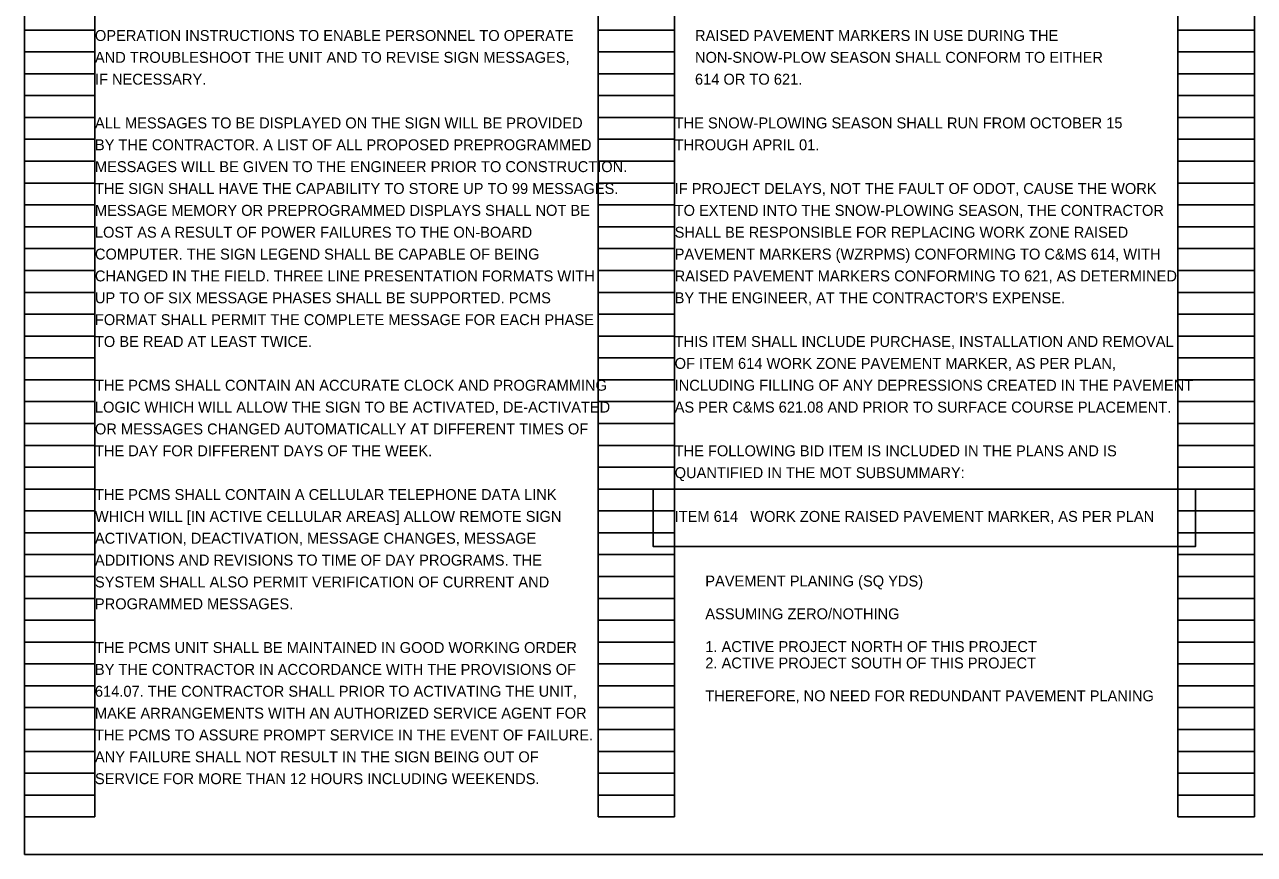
# Model space of a CAD drawing. Extents: x 1820207 to 1820557, y 740216 to 740315.
# Drawn here: x 1820297.23 to 1820312.97, y 740254.74 to 740265.37 of the extents above; entities that cross this region are included whole.
import ezdxf

# ---------------------------------------------------------------- set-up
doc = ezdxf.new("R2010")
doc.units = 0
for name, color, linetype in [('SC_Scratch1', 7, 'Continuous'), ('SC_Scratch2', 7, 'Continuous'), ('SC_Shading1', 7, 'Continuous'), ('SH_Text', 7, 'Continuous')]:
    doc.layers.add(name, color=color, linetype=linetype)

msp = doc.modelspace()

# ---------------------------------------------------------------- linework, layer by layer
at = {"layer": 'SC_Scratch1'}
for p, q in [((1820297.234, 740255.222), (1820297.234, 740275.382)), ((1820298.134, 740255.222), (1820298.134, 740275.382)), ((1820304.574, 740255.222), (1820304.574, 740275.382)), ((1820305.554, 740255.222), (1820305.554, 740275.382)), ((1820311.994, 740255.222), (1820311.994, 740275.382)), ((1820312.974, 740255.222), (1820312.974, 740275.382)), ((1820297.234, 740265.302), (1820298.134, 740265.302)), ((1820304.574, 740265.302), (1820305.554, 740265.302)), ((1820311.994, 740265.302), (1820312.974, 740265.302)), ((1820297.234, 740265.022), (1820298.134, 740265.022)), ((1820304.574, 740265.022), (1820305.554, 740265.022)), ((1820311.994, 740265.022), (1820312.974, 740265.022)), ((1820297.234, 740264.742), (1820298.134, 740264.742)), ((1820304.574, 740264.742), (1820305.554, 740264.742)), ((1820311.994, 740264.742), (1820312.974, 740264.742)), ((1820297.234, 740264.462), (1820298.134, 740264.462)), ((1820304.574, 740264.462), (1820305.554, 740264.462)), ((1820311.994, 740264.462), (1820312.974, 740264.462)), ((1820297.234, 740264.182), (1820298.134, 740264.182)), ((1820304.574, 740264.182), (1820305.554, 740264.182)), ((1820311.994, 740264.182), (1820312.974, 740264.182)), ((1820297.234, 740263.902), (1820298.134, 740263.902)), ((1820304.574, 740263.902), (1820305.554, 740263.902)), ((1820311.994, 740263.902), (1820312.974, 740263.902)), ((1820297.234, 740263.622), (1820298.134, 740263.622)), ((1820304.574, 740263.622), (1820305.554, 740263.622)), ((1820311.994, 740263.622), (1820312.974, 740263.622)), ((1820297.234, 740263.342), (1820298.134, 740263.342)), ((1820304.574, 740263.342), (1820305.554, 740263.342)), ((1820311.994, 740263.342), (1820312.974, 740263.342)), ((1820297.234, 740263.062), (1820298.134, 740263.062)), ((1820304.574, 740263.062), (1820305.554, 740263.062)), ((1820311.994, 740263.062), (1820312.974, 740263.062)), ((1820297.234, 740262.782), (1820298.134, 740262.782)), ((1820304.574, 740262.782), (1820305.554, 740262.782)), ((1820311.994, 740262.782), (1820312.974, 740262.782)), ((1820297.234, 740262.502), (1820298.134, 740262.502)), ((1820304.574, 740262.502), (1820305.554, 740262.502)), ((1820311.994, 740262.502), (1820312.974, 740262.502)), ((1820297.234, 740262.222), (1820298.134, 740262.222)), ((1820304.574, 740262.222), (1820305.554, 740262.222)), ((1820311.994, 740262.222), (1820312.974, 740262.222)), ((1820297.234, 740261.942), (1820298.134, 740261.942)), ((1820304.574, 740261.942), (1820305.554, 740261.942)), ((1820311.994, 740261.942), (1820312.974, 740261.942)), ((1820297.234, 740261.662), (1820298.134, 740261.662)), ((1820304.574, 740261.662), (1820305.554, 740261.662)), ((1820311.994, 740261.662), (1820312.974, 740261.662)), ((1820297.234, 740261.382), (1820298.134, 740261.382)), ((1820304.574, 740261.382), (1820305.554, 740261.382)), ((1820311.994, 740261.382), (1820312.974, 740261.382)), ((1820297.234, 740261.102), (1820298.134, 740261.102)), ((1820304.574, 740261.102), (1820305.554, 740261.102)), ((1820311.994, 740261.102), (1820312.974, 740261.102)), ((1820297.234, 740260.822), (1820298.134, 740260.822)), ((1820304.574, 740260.822), (1820305.554, 740260.822)), ((1820311.994, 740260.822), (1820312.974, 740260.822)), ((1820297.234, 740260.542), (1820298.134, 740260.542)), ((1820304.574, 740260.542), (1820305.554, 740260.542)), ((1820311.994, 740260.542), (1820312.974, 740260.542)), ((1820297.234, 740260.262), (1820298.134, 740260.262)), ((1820304.574, 740260.262), (1820305.554, 740260.262)), ((1820311.994, 740260.262), (1820312.974, 740260.262)), ((1820297.234, 740259.982), (1820298.134, 740259.982)), ((1820304.574, 740259.982), (1820305.554, 740259.982)), ((1820311.994, 740259.982), (1820312.974, 740259.982)), ((1820297.234, 740259.702), (1820298.134, 740259.702)), ((1820304.574, 740259.702), (1820305.554, 740259.702)), ((1820311.994, 740259.702), (1820312.974, 740259.702)), ((1820297.234, 740259.422), (1820298.134, 740259.422)), ((1820304.574, 740259.422), (1820305.554, 740259.422)), ((1820311.994, 740259.422), (1820312.974, 740259.422)), ((1820297.234, 740259.142), (1820298.134, 740259.142)), ((1820304.574, 740259.142), (1820305.554, 740259.142)), ((1820311.994, 740259.142), (1820312.974, 740259.142)), ((1820297.234, 740258.862), (1820298.134, 740258.862)), ((1820304.574, 740258.862), (1820305.554, 740258.862)), ((1820311.994, 740258.862), (1820312.974, 740258.862)), ((1820297.234, 740258.582), (1820298.134, 740258.582)), ((1820304.574, 740258.582), (1820305.554, 740258.582)), ((1820311.994, 740258.582), (1820312.974, 740258.582)), ((1820297.234, 740258.302), (1820298.134, 740258.302)), ((1820304.574, 740258.302), (1820305.554, 740258.302)), ((1820311.994, 740258.302), (1820312.974, 740258.302)), ((1820297.234, 740258.022), (1820298.134, 740258.022)), ((1820304.574, 740258.022), (1820305.554, 740258.022)), ((1820311.994, 740258.022), (1820312.974, 740258.022)), ((1820297.234, 740257.742), (1820298.134, 740257.742)), ((1820304.574, 740257.742), (1820305.554, 740257.742)), ((1820311.994, 740257.742), (1820312.974, 740257.742)), ((1820297.234, 740257.462), (1820298.134, 740257.462)), ((1820304.574, 740257.462), (1820305.554, 740257.462)), ((1820311.994, 740257.462), (1820312.974, 740257.462)), ((1820297.234, 740257.182), (1820298.134, 740257.182)), ((1820304.574, 740257.182), (1820305.554, 740257.182)), ((1820311.994, 740257.182), (1820312.974, 740257.182)), ((1820297.234, 740256.902), (1820298.134, 740256.902)), ((1820304.574, 740256.902), (1820305.554, 740256.902)), ((1820311.994, 740256.902), (1820312.974, 740256.902)), ((1820297.234, 740256.622), (1820298.134, 740256.622)), ((1820304.574, 740256.622), (1820305.554, 740256.622)), ((1820311.994, 740256.622), (1820312.974, 740256.622)), ((1820297.234, 740256.342), (1820298.134, 740256.342)), ((1820304.574, 740256.342), (1820305.554, 740256.342)), ((1820311.994, 740256.342), (1820312.974, 740256.342)), ((1820297.234, 740256.062), (1820298.134, 740256.062)), ((1820304.574, 740256.062), (1820305.554, 740256.062)), ((1820311.994, 740256.062), (1820312.974, 740256.062)), ((1820297.234, 740255.782), (1820298.134, 740255.782)), ((1820304.574, 740255.782), (1820305.554, 740255.782)), ((1820311.994, 740255.782), (1820312.974, 740255.782)), ((1820297.234, 740255.502), (1820298.134, 740255.502)), ((1820304.574, 740255.502), (1820305.554, 740255.502)), ((1820311.994, 740255.502), (1820312.974, 740255.502)), ((1820297.234, 740255.222), (1820298.134, 740255.222)), ((1820304.574, 740255.222), (1820305.554, 740255.222)), ((1820311.994, 740255.222), (1820312.974, 740255.222))]:
    msp.add_line(p, q, dxfattribs=at)
at = {"layer": 'SC_Scratch2'}
msp.add_lwpolyline([(1820297.234, 740275.742), (1820327.734, 740275.742), (1820327.734, 740254.742), (1820297.234, 740254.742)], close=True, dxfattribs=at)
at = {"layer": 'SC_Shading1'}
msp.add_lwpolyline([(1820305.279, 740259.422), (1820312.218, 740259.422), (1820312.218, 740258.686), (1820305.279, 740258.686)], close=True, dxfattribs=at)

# ---------------------------------------------------------------- texts
for s, p in [('PAVEMENT PLANING (SQ YDS)', (1820305.946, 740258.174)), ('ASSUMING ZERO/NOTHING', (1820305.946, 740257.754)), ('1. ACTIVE PROJECT NORTH OF THIS PROJECT', (1820305.946, 740257.334)), ('2. ACTIVE PROJECT SOUTH OF THIS PROJECT', (1820305.946, 740257.124)), ('THEREFORE, NO NEED FOR REDUNDANT PAVEMENT PLANING', (1820305.946, 740256.704))]:
    msp.add_text(s, height=0.14, dxfattribs=at).set_placement(p)
at = {"layer": 'SH_Text'}
for s, p in [('OPERATION INSTRUCTIONS TO ENABLE PERSONNEL TO OPERATE ', (1820298.134, 740265.162)), ('     RAISED PAVEMENT MARKERS IN USE DURING THE', (1820305.554, 740265.162)), ('AND TROUBLESHOOT THE UNIT AND TO REVISE SIGN MESSAGES, ', (1820298.134, 740264.882)), ('     NON-SNOW-PLOW SEASON SHALL CONFORM TO EITHER', (1820305.554, 740264.882)), ('IF NECESSARY.', (1820298.134, 740264.602)), ('     614 OR TO 621.', (1820305.554, 740264.602)), ('ALL MESSAGES TO BE DISPLAYED ON THE SIGN WILL BE PROVIDED ', (1820298.134, 740264.042)), ('THE SNOW-PLOWING SEASON SHALL RUN FROM OCTOBER 15', (1820305.554, 740264.042)), ('BY THE CONTRACTOR. A LIST OF ALL PROPOSED PREPROGRAMMED ', (1820298.134, 740263.762)), ('THROUGH APRIL 01.', (1820305.554, 740263.762)), ('MESSAGES WILL BE GIVEN TO THE ENGINEER PRIOR TO CONSTRUCTION. ', (1820298.134, 740263.482)), ('THE SIGN SHALL HAVE THE CAPABILITY TO STORE UP TO 99 MESSAGES. ', (1820298.134, 740263.202)), ('IF PROJECT DELAYS, NOT THE FAULT OF ODOT, CAUSE THE WORK ', (1820305.554, 740263.202)), ('MESSAGE MEMORY OR PREPROGRAMMED DISPLAYS SHALL NOT BE ', (1820298.134, 740262.922)), ('TO EXTEND INTO THE SNOW-PLOWING SEASON, THE CONTRACTOR ', (1820305.554, 740262.922)), ('LOST AS A RESULT OF POWER FAILURES TO THE ON-BOARD ', (1820298.134, 740262.642)), ('SHALL BE RESPONSIBLE FOR REPLACING WORK ZONE RAISED ', (1820305.554, 740262.642)), ('COMPUTER. THE SIGN LEGEND SHALL BE CAPABLE OF BEING ', (1820298.134, 740262.362)), ('PAVEMENT MARKERS (WZRPMS) CONFORMING TO C&MS 614, WITH ', (1820305.554, 740262.362)), ('CHANGED IN THE FIELD. THREE LINE PRESENTATION FORMATS WITH ', (1820298.134, 740262.082)), ('RAISED PAVEMENT MARKERS CONFORMING TO 621, AS DETERMINED ', (1820305.554, 740262.082)), ('UP TO OF SIX MESSAGE PHASES SHALL BE SUPPORTED. PCMS ', (1820298.134, 740261.802)), ("BY THE ENGINEER, AT THE CONTRACTOR'S EXPENSE.", (1820305.554, 740261.802)), ('FORMAT SHALL PERMIT THE COMPLETE MESSAGE FOR EACH PHASE ', (1820298.134, 740261.522)), ('TO BE READ AT LEAST TWICE. ', (1820298.134, 740261.242)), ('THIS ITEM SHALL INCLUDE PURCHASE, INSTALLATION AND REMOVAL', (1820305.554, 740261.242)), ('OF ITEM 614 WORK ZONE PAVEMENT MARKER, AS PER PLAN, ', (1820305.554, 740260.962)), ('THE PCMS SHALL CONTAIN AN ACCURATE CLOCK AND PROGRAMMING ', (1820298.134, 740260.682)), ('INCLUDING FILLING OF ANY DEPRESSIONS CREATED IN THE PAVEMENT ', (1820305.554, 740260.682)), ('LOGIC WHICH WILL ALLOW THE SIGN TO BE ACTIVATED, DE-ACTIVATED ', (1820298.134, 740260.402)), ('AS PER C&MS 621.08 AND PRIOR TO SURFACE COURSE PLACEMENT.', (1820305.554, 740260.402)), ('OR MESSAGES CHANGED AUTOMATICALLY AT DIFFERENT TIMES OF ', (1820298.134, 740260.122)), ('THE DAY FOR DIFFERENT DAYS OF THE WEEK.', (1820298.134, 740259.842)), ('THE FOLLOWING BID ITEM IS INCLUDED IN THE PLANS AND IS ', (1820305.554, 740259.842)), ('QUANTIFIED IN THE MOT SUBSUMMARY:', (1820305.554, 740259.562)), ('THE PCMS SHALL CONTAIN A CELLULAR TELEPHONE DATA LINK ', (1820298.134, 740259.282)), ('WHICH WILL [IN ACTIVE CELLULAR AREAS] ALLOW REMOTE SIGN ', (1820298.134, 740259.002)), ('ITEM 614   WORK ZONE RAISED PAVEMENT MARKER, AS PER PLAN', (1820305.554, 740259.002)), ('ACTIVATION, DEACTIVATION, MESSAGE CHANGES, MESSAGE ', (1820298.134, 740258.722)), ('ADDITIONS AND REVISIONS TO TIME OF DAY PROGRAMS. THE ', (1820298.134, 740258.442)), ('SYSTEM SHALL ALSO PERMIT VERIFICATION OF CURRENT AND ', (1820298.134, 740258.162)), ('PROGRAMMED MESSAGES.', (1820298.134, 740257.882)), ('THE PCMS UNIT SHALL BE MAINTAINED IN GOOD WORKING ORDER ', (1820298.134, 740257.322)), ('BY THE CONTRACTOR IN ACCORDANCE WITH THE PROVISIONS OF ', (1820298.134, 740257.042)), ('614.07. THE CONTRACTOR SHALL PRIOR TO ACTIVATING THE UNIT, ', (1820298.134, 740256.762)), ('MAKE ARRANGEMENTS WITH AN AUTHORIZED SERVICE AGENT FOR ', (1820298.134, 740256.482)), ('THE PCMS TO ASSURE PROMPT SERVICE IN THE EVENT OF FAILURE. ', (1820298.134, 740256.202)), ('ANY FAILURE SHALL NOT RESULT IN THE SIGN BEING OUT OF ', (1820298.134, 740255.922)), ('SERVICE FOR MORE THAN 12 HOURS INCLUDING WEEKENDS. ', (1820298.134, 740255.642))]:
    msp.add_text(s, height=0.14, dxfattribs=at).set_placement(p)

doc.saveas('drawing.dxf')
